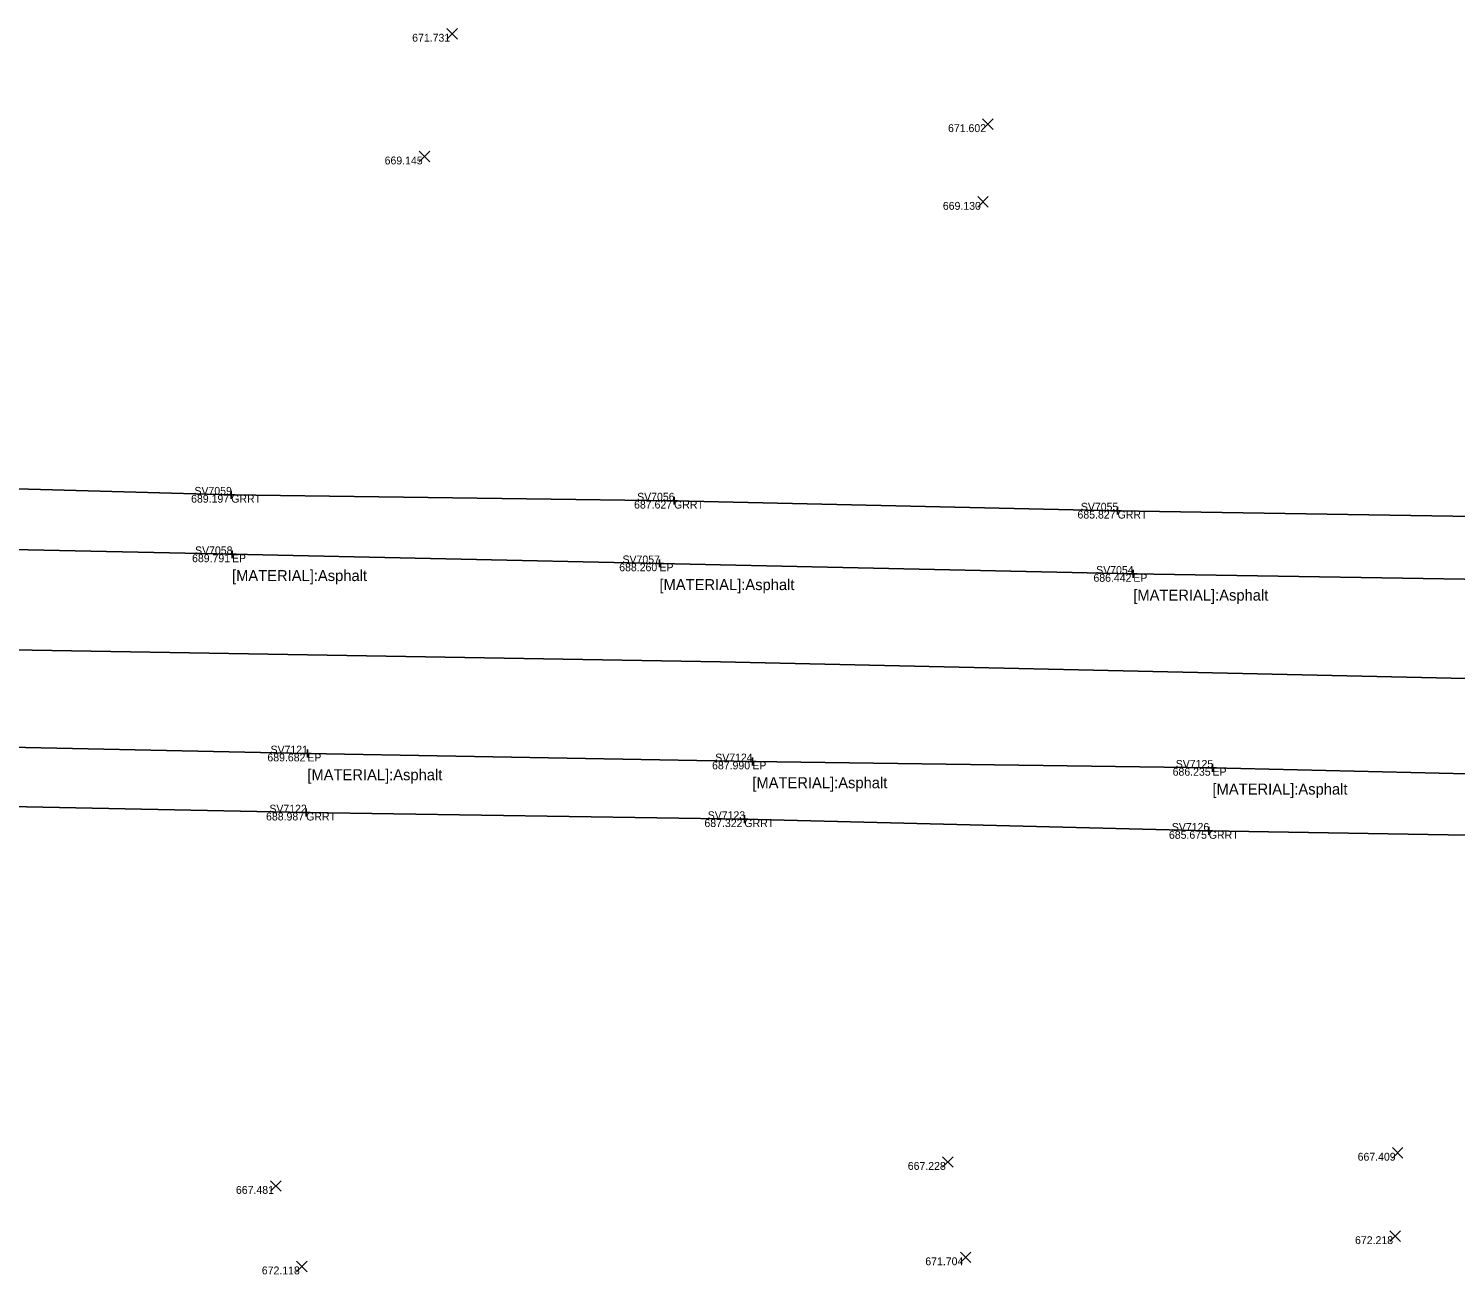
# Model space of a CAD drawing. Extents: x 1659932 to 1663108, y 619867 to 620611.
# Drawn here: x 1661805.2 to 1661986.7, y 620143.1 to 620301.5 of the extents above; entities that cross this region are included whole.
import ezdxf

# ---------------------------------------------------------------- set-up
doc = ezdxf.new("R2010")
doc.units = 0
for name, color, linetype in [('PM_X_CL_Dashed', 7, 'Continuous'), ('PV_X_EOP', 7, 'Continuous'), ('RD_X_GR_Rt', 7, 'Continuous'), ('SV_X_Random_Point', 7, 'Continuous'), ('SV_X_Shot_Marker', 7, 'Continuous'), ('SV_X_Text', 7, 'Continuous'), ('SV_X_Text_Comment', 7, 'Continuous'), ('SV_X_Text_Elevation', 7, 'Continuous'), ('SV_X_Text_Name', 7, 'Continuous')]:
    doc.layers.add(name, color=color, linetype=linetype)

msp = doc.modelspace()

# ---------------------------------------------------------------- linework, layer by layer
at = {"layer": 'PM_X_CL_Dashed'}
msp.add_lwpolyline([(1661548.68, 620227.77), (1661669.96, 620225.42), (1661783.14, 620222.83), (1661893.22, 620220.99), (1661995.64, 620218.69), (1662098.65, 620216.83), (1662208.49, 620214.49), (1662310.47, 620212.73), (1662401.36, 620210.77), (1662501.77, 620209.17), (1662614.52, 620207.13), (1662727.83, 620205.67), (1662841.02, 620204.32), (1662955.43, 620202.56), (1663049.21, 620201.36)], dxfattribs=at)
at = {"layer": 'PV_X_EOP'}
for points in [[(1662111.67, 620229.32), (1662054.93, 620230.37), (1661998.42, 620231.32), (1661945.73, 620232.16), (1661885.47, 620233.5), (1661831.11, 620234.65), (1661773.24, 620235.9), (1661719.2, 620236.82), (1661662.34, 620238.11), (1661602.46, 620239.35), (1661551.29, 620241.52)], [(1661543.6, 620215.08), (1661595.45, 620214.35), (1661653.94, 620213.41), (1661707.72, 620212.24), (1661760.97, 620211.02), (1661840.69, 620209.32), (1661897.28, 620208.31), (1661955.8, 620207.5), (1662009.84, 620206.22), (1662063.33, 620205.17), (1662115.71, 620204.21)]]:
    msp.add_lwpolyline(points, dxfattribs=at)
at = {"layer": 'RD_X_GR_Rt'}
for points in [[(1662112.15, 620237.06), (1662055.66, 620238.25), (1661999.68, 620239.27), (1661943.73, 620240.2), (1661887.33, 620241.47), (1661831.01, 620242.22), (1661774.89, 620243.8), (1661718.6, 620244.37), (1661662.44, 620245.38), (1661601.89, 620244.64), (1661537.84, 620244.62)], [(1661527.71, 620211.76), (1661596.63, 620209.07), (1661652.77, 620205.71), (1661709.09, 620204.45), (1661758.9, 620203.47), (1661840.54, 620201.81), (1661896.27, 620200.97), (1661955.33, 620199.48), (1662008.56, 620198.59), (1662063.03, 620197.38), (1662114.92, 620196.42)]]:
    msp.add_lwpolyline(points, dxfattribs=at)
at = {"layer": 'SV_X_Random_Point'}
for p, q in [((1661858.43, 620300.17), (1661859.77, 620301.51)), ((1661858.43, 620301.51), (1661859.77, 620300.17)), ((1661926.57, 620288.68), (1661927.91, 620290.01)), ((1661926.57, 620290.01), (1661927.91, 620288.68)), ((1661854.92, 620284.57), (1661856.26, 620285.9)), ((1661854.92, 620285.9), (1661856.26, 620284.57)), ((1661925.96, 620278.79), (1661927.29, 620280.13)), ((1661925.96, 620280.13), (1661927.29, 620278.79)), ((1661921.48, 620156.71), (1661922.82, 620158.05)), ((1661921.48, 620158.05), (1661922.82, 620156.71)), ((1661978.68, 620157.88), (1661980.01, 620159.21)), ((1661978.68, 620159.21), (1661980.01, 620157.88)), ((1661836.02, 620153.66), (1661837.35, 620155)), ((1661836.02, 620155), (1661837.35, 620153.66)), ((1661978.36, 620147.27), (1661979.69, 620148.61)), ((1661978.36, 620148.61), (1661979.69, 620147.27)), ((1661923.74, 620144.58), (1661925.07, 620145.92)), ((1661923.74, 620145.92), (1661925.07, 620144.58)), ((1661839.33, 620143.43), (1661840.67, 620144.76)), ((1661839.33, 620144.76), (1661840.67, 620143.43))]:
    msp.add_line(p, q, dxfattribs=at)
at = {"layer": 'SV_X_Shot_Marker'}
for p, q in [((1661830.51, 620242.22), (1661831.51, 620242.22)), ((1661831.01, 620242.72), (1661831.01, 620241.72)), ((1661831.01, 620242.22), (1661831.01, 620242.22)), ((1661886.83, 620241.47), (1661887.83, 620241.47)), ((1661887.33, 620241.97), (1661887.33, 620240.97)), ((1661887.33, 620241.47), (1661887.33, 620241.47)), ((1661943.23, 620240.2), (1661944.23, 620240.2)), ((1661943.73, 620240.7), (1661943.73, 620239.7)), ((1661943.73, 620240.2), (1661943.73, 620240.2)), ((1661830.61, 620234.65), (1661831.61, 620234.65)), ((1661831.11, 620235.15), (1661831.11, 620234.15)), ((1661831.11, 620234.65), (1661831.11, 620234.65)), ((1661884.97, 620233.5), (1661885.97, 620233.5)), ((1661885.47, 620234), (1661885.47, 620233)), ((1661885.47, 620233.5), (1661885.47, 620233.5)), ((1661945.73, 620232.66), (1661945.73, 620231.66)), ((1661945.23, 620232.16), (1661946.23, 620232.16)), ((1661945.73, 620232.16), (1661945.73, 620232.16)), ((1661840.19, 620209.32), (1661841.19, 620209.32)), ((1661840.69, 620209.82), (1661840.69, 620208.82)), ((1661840.69, 620209.32), (1661840.69, 620209.32)), ((1661897.28, 620208.81), (1661897.28, 620207.81)), ((1661896.78, 620208.31), (1661897.78, 620208.31)), ((1661897.28, 620208.31), (1661897.28, 620208.31)), ((1661955.3, 620207.5), (1661956.3, 620207.5)), ((1661955.8, 620208), (1661955.8, 620207)), ((1661955.8, 620207.5), (1661955.8, 620207.5)), ((1661840.04, 620201.81), (1661841.04, 620201.81)), ((1661840.54, 620202.31), (1661840.54, 620201.31)), ((1661840.54, 620201.81), (1661840.54, 620201.81)), ((1661895.77, 620200.97), (1661896.77, 620200.97)), ((1661896.27, 620201.47), (1661896.27, 620200.47)), ((1661896.27, 620200.97), (1661896.27, 620200.97)), ((1661955.33, 620199.98), (1661955.33, 620198.98)), ((1661954.83, 620199.48), (1661955.83, 620199.48)), ((1661955.33, 620199.48), (1661955.33, 620199.48))]:
    msp.add_line(p, q, dxfattribs=at)

# ---------------------------------------------------------------- texts
at = {"layer": 'SV_X_Text'}
for p in [(1661831.11, 620231.25), (1661885.47, 620230.1), (1661945.73, 620228.76), (1661840.69, 620205.92), (1661897.28, 620204.91), (1661955.8, 620204.1)]:
    msp.add_text('[MATERIAL]:Asphalt', height=1.4, dxfattribs=at).set_placement(p)
at = {"layer": 'SV_X_Text_Comment'}
for s, p in [('GRRT', (1661831.01, 620241.22)), ('GRRT', (1661887.33, 620240.47)), ('GRRT', (1661943.73, 620239.2)), ('EP', (1661831.11, 620233.65)), ('EP', (1661885.47, 620232.5)), ('EP', (1661945.73, 620231.16)), ('EP', (1661840.69, 620208.32)), ('EP', (1661897.28, 620207.31)), ('EP', (1661955.8, 620206.5)), ('GRRT', (1661840.54, 620200.81)), ('GRRT', (1661896.27, 620199.97)), ('GRRT', (1661955.33, 620198.48))]:
    msp.add_text(s, height=1, dxfattribs=at).set_placement(p)
at = {"layer": 'SV_X_Text_Elevation'}
for s, p in [('671.731', (1661854.02, 620299.84)), ('671.602', (1661922.17, 620288.34)), ('669.145', (1661850.52, 620284.23)), ('669.130', (1661921.51, 620278.46)), ('689.197', (1661825.91, 620241.22)), ('687.627', (1661882.24, 620240.47)), ('685.827', (1661938.63, 620239.2)), ('689.791', (1661826.03, 620233.65)), ('688.260', (1661880.35, 620232.5)), ('686.442', (1661940.66, 620231.16)), ('689.682', (1661835.61, 620208.32)), ('687.990', (1661892.16, 620207.31)), ('686.235', (1661950.73, 620206.5)), ('688.987', (1661835.44, 620200.81)), ('687.322', (1661891.19, 620199.97)), ('685.675', (1661950.26, 620198.48)), ('667.409', (1661974.26, 620157.55)), ('667.228', (1661917.05, 620156.38)), ('667.481', (1661831.61, 620153.33)), ('672.218', (1661973.93, 620146.94)), ('671.704', (1661919.28, 620144.25)), ('672.118', (1661834.9, 620143.09))]:
    msp.add_text(s, height=1, dxfattribs=at).set_placement(p)
at = {"layer": 'SV_X_Text_Name'}
for s, p in [('SV7059', (1661826.33, 620242.22)), ('SV7056', (1661882.63, 620241.47)), ('SV7055', (1661939.06, 620240.2)), ('SV7058', (1661826.41, 620234.65)), ('SV7057', (1661880.77, 620233.5)), ('SV7054', (1661941.01, 620232.16)), ('SV7121', (1661836.01, 620209.32)), ('SV7124', (1661892.56, 620208.31)), ('SV7125', (1661951.13, 620207.5)), ('SV7122', (1661835.86, 620201.81)), ('SV7123', (1661891.61, 620200.97)), ('SV7126', (1661950.63, 620199.48))]:
    msp.add_text(s, height=1, dxfattribs=at).set_placement(p)

doc.saveas('drawing.dxf')
